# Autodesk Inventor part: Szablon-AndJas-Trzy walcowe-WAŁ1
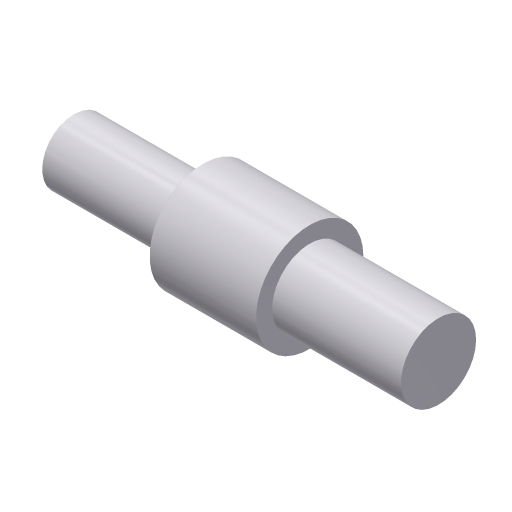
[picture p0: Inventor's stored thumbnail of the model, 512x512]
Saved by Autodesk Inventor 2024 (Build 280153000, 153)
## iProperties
Company: ATC
CustomPartVersion: 1
Created: 2023-03
Part Number: Szablon-AndJas-Trzy walcowe-WAŁ1
Material: Steel
Document SubType Name: Modeling
Designer: Andrzej Jaskulski
Density: 1 g/cm^3
Appearance: Kurs-AJ
Checked By: A.J.
Engr Approved By: Andrzej Jaskulski
Mfg Approved By: Andrzej Jaskulski
Authority: A.J.
Author: Andrzej Jaskulski
Title: A.J.: Kurs R2024-MEP
Revision Number: 1/24
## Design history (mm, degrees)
sketch "Szkic główny"
  geometry: L1 (0, 0)-(170, 0) reference; L2 (0, 0)-(0, 15); L3 (0, 15)-(60, 15); L4 (60, 15)-(60, 25); L5 (110, 25)-(110, 17.5); L6 (60, 25)-(110, 25); L7 (170, 17.5)-(170, 0); L8 (110, 17.5)-(170, 17.5)
  constraints: 16 end point, 5 horizontal, 4 vertical
  dimensions: "d3" = 30 diameter of L3 L1 (derived); "d4" = 50 diameter of L6 L1 (derived); "d5" = 35 diameter of L8 L1 (derived)
revolve "Obrót1" sketch "Szkic główny" stored, may be unused: angle "d6" = 0 deg
chamfer "Faza1" distance "d7" = 0.5; stored, may be unused: second distance "d8" = 0.125, angle "d9" = 45 deg
fillet "Zaokrąglenie1" dims "d10" = 5
chamfer "Faza2" distance "d11" = 0.5; stored, may be unused: second distance "d12" = 0.125, angle "d13" = 45 deg
node "Bryła1"
other parameters: "d0" = 0, "d1" = 0, "d2" = 0
